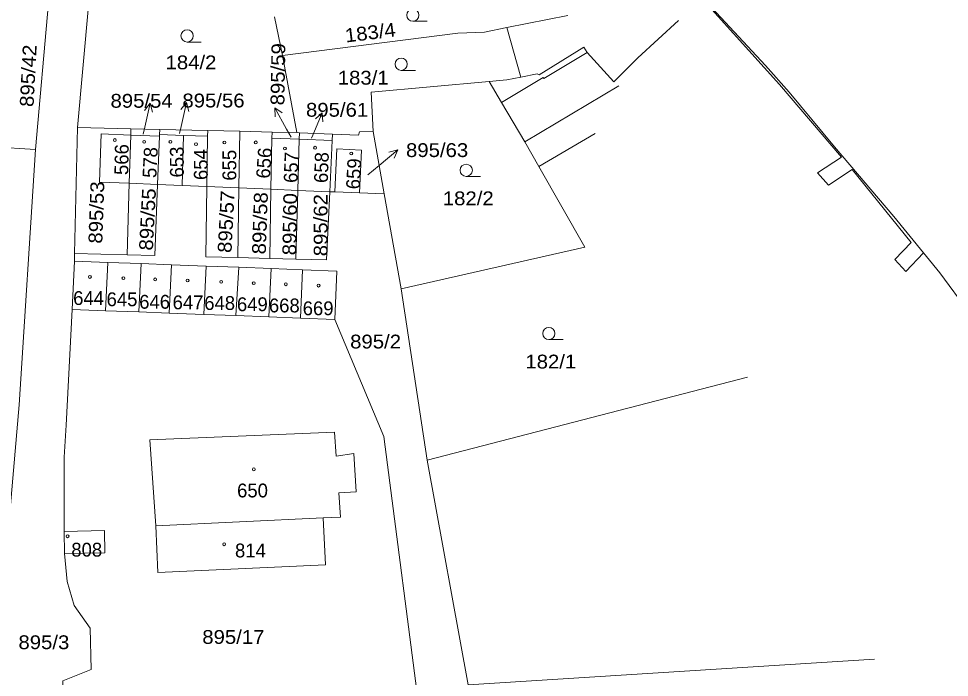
# Model space of a CAD drawing. Extents: x -686207 to -681951, y -1020493 to -1017811.
# Drawn here: x -682393.2 to -682278.7, y -1019020.1 to -1018939.1 of the extents above; entities that cross this region are included whole.
import ezdxf

# ---------------------------------------------------------------- set-up
doc = ezdxf.new("R2010")
doc.units = 0
doc.header["$LTSCALE"] = 0.4
for name, color, linetype, lineweight in [('1', 7, 'Continuous', 13), ('13', 7, 'Continuous', 13), ('3', 7, 'Continuous', 13), ('4', 7, 'Continuous', 13), ('5', 7, 'Continuous', 13), ('7', 7, 'Continuous', 13)]:
    doc.layers.add(name, color=color, linetype=linetype, lineweight=lineweight)
doc.layers.add('2', color=7, linetype='Continuous')

msp = doc.modelspace()

# ---------------------------------------------------------------- linework, layer by layer
at = {"layer": '1'}
for p, q in [((-682361.73, -1018938.86), (-682360.73, -1018943.62)), ((-682325.63, -1018938.69), (-682333.17, -1018940.2)), ((-682333.17, -1018940.2), (-682331.42, -1018946.27)), ((-682360.73, -1018943.62), (-682358.97, -1018953.11)), ((-682385.94, -1018952.47), (-682379.38, -1018952.63)), ((-682375.87, -1018953.34), (-682375.84, -1018952.71)), ((-682375.84, -1018952.71), (-682369.92, -1018952.85)), ((-682375.88, -1018953.53), (-682379.4, -1018953.4)), ((-682375.87, -1018953.34), (-682375.88, -1018953.53)), ((-682372.91, -1018953.45), (-682375.87, -1018953.34)), ((-682373.06, -1018959.61), (-682372.91, -1018953.45)), ((-682369.95, -1018953.56), (-682372.91, -1018953.45)), ((-682370.04, -1018959.74), (-682369.95, -1018953.56)), ((-682369.92, -1018952.85), (-682369.95, -1018953.56)), ((-682369.92, -1018952.85), (-682365.98, -1018952.94)), ((-682366.1, -1018959.9), (-682365.98, -1018952.94)), ((-682365.98, -1018952.94), (-682362.03, -1018953.04)), ((-682362.05, -1018953.79), (-682362.16, -1018960.07)), ((-682362.03, -1018953.04), (-682358.97, -1018953.11)), ((-682358.97, -1018953.11), (-682358.66, -1018953.12)), ((-682358.66, -1018953.12), (-682354.58, -1018953.28)), ((-682354.62, -1018954.08), (-682354.58, -1018953.28)), ((-682349.59, -1018952.99), (-682348.23, -1018960.64)), ((-682379.85, -1018968.13), (-682379.58, -1018959.33)), ((-682376.1, -1018959.48), (-682373.06, -1018959.61)), ((-682373.06, -1018959.61), (-682370.04, -1018959.74)), ((-682370.04, -1018959.74), (-682366.1, -1018959.9)), ((-682366.1, -1018959.9), (-682362.16, -1018960.07)), ((-682359.08, -1018968.66), (-682358.85, -1018960.21)), ((-682354.29, -1018960.4), (-682354.93, -1018960.37)), ((-682348.23, -1018960.64), (-682351.26, -1018960.52)), ((-682348.23, -1018960.64), (-682346.16, -1018972.32)), ((-682379.85, -1018968.13), (-682386.3, -1018967.97)), ((-682386.32, -1018968.9), (-682386.61, -1018974.84)), ((-682382.23, -1018969.06), (-682386.32, -1018968.9)), ((-682382.49, -1018975), (-682382.23, -1018969.06)), ((-682378.11, -1018969.22), (-682382.23, -1018969.06)), ((-682378.39, -1018975.15), (-682378.11, -1018969.22)), ((-682374.68, -1018975.29), (-682374.41, -1018969.36)), ((-682370.4, -1018975.46), (-682370.14, -1018969.52)), ((-682366.12, -1018969.67), (-682370.14, -1018969.52)), ((-682366.46, -1018975.61), (-682366.12, -1018969.67)), ((-682362.12, -1018969.82), (-682366.12, -1018969.67)), ((-682362.41, -1018975.76), (-682362.12, -1018969.82)), ((-682358.28, -1018969.97), (-682362.12, -1018969.82)), ((-682358.53, -1018975.91), (-682358.28, -1018969.97)), ((-682346.16, -1018972.32), (-682342.94, -1018993.38)), ((-682382.49, -1018975), (-682378.39, -1018975.15)), ((-682366.46, -1018975.61), (-682362.41, -1018975.76)), ((-682362.41, -1018975.76), (-682358.53, -1018975.91)), ((-682358.53, -1018975.91), (-682354.3, -1018976.07)), ((-682303.55, -1018983.18), (-682342.94, -1018993.38)), ((-682376.33, -1019001.45), (-682355.73, -1019000.49)), ((-682387.59, -1019002.15), (-682387.56, -1019004.85)), ((-682337.89, -1019021), (-682287.95, -1019017.83))]:
    msp.add_line(p, q, dxfattribs=at)
for points in [[(-682276.34, -1018975.17), (-682279.9, -1018970.36), (-682285.55, -1018963.44), (-682292.84, -1018954.85), (-682298.41, -1018948.14), (-682301.32, -1018944.85), (-682314.55, -1018930.63), (-682342.21, -1018901.37), (-682348.46, -1018895.5), (-682353.78, -1018891.13), (-682359.01, -1018887.98), (-682365.23, -1018884.61), (-682377.11, -1018878.94), (-682378.97, -1018879.84), (-682381.2, -1018881.17)], [(-682383.5, -1018926.17), (-682384.6, -1018937.53), (-682385.94, -1018952.47)], [(-682389.52, -1018937.15), (-682391.12, -1018955.18), (-682396.38, -1018954.85)], [(-682331.42, -1018946.27), (-682329.42, -1018945.86), (-682329.18, -1018945.99), (-682323.67, -1018942.62), (-682323.29, -1018943.26), (-682320.01, -1018946.88), (-682319.8, -1018946.67), (-682317.04, -1018943.92), (-682312.04, -1018939.32)], [(-682333.17, -1018940.2), (-682335.91, -1018940.75), (-682339.16, -1018940.89), (-682360.73, -1018943.62)], [(-682335.31, -1018946.82), (-682349.85, -1018948.12), (-682349.59, -1018952.99)], [(-682335.31, -1018946.82), (-682333.79, -1018949.39), (-682330.92, -1018954.26), (-682329.2, -1018957.27), (-682323.56, -1018967.21), (-682346.16, -1018972.32)], [(-682331.42, -1018946.27), (-682333.14, -1018946.62), (-682335.31, -1018946.82)], [(-682386.32, -1018968.9), (-682386.3, -1018967.97), (-682385.94, -1018952.47)], [(-682379.4, -1018953.4), (-682379.38, -1018952.63), (-682375.84, -1018952.71)], [(-682379.58, -1018959.33), (-682376.1, -1018959.48), (-682375.88, -1018953.53)], [(-682358.68, -1018953.92), (-682362.05, -1018953.79), (-682362.03, -1018953.04)], [(-682358.85, -1018960.21), (-682358.68, -1018953.92), (-682358.66, -1018953.12)], [(-682354.58, -1018953.28), (-682351.4, -1018953.4), (-682351.27, -1018953.02), (-682349.59, -1018952.99)], [(-682358.85, -1018960.21), (-682354.93, -1018960.37), (-682354.62, -1018954.08), (-682358.68, -1018953.92)], [(-682376.1, -1018959.48), (-682376.42, -1018968.22), (-682379.85, -1018968.13)], [(-682366.25, -1018968.48), (-682370.17, -1018968.38), (-682370.04, -1018959.74)], [(-682362.31, -1018968.58), (-682366.25, -1018968.48), (-682366.1, -1018959.9)], [(-682359.08, -1018968.66), (-682362.31, -1018968.58), (-682362.16, -1018960.07), (-682358.85, -1018960.21)], [(-682354.93, -1018960.37), (-682355.34, -1018968.76), (-682359.08, -1018968.66)], [(-682370.14, -1018969.52), (-682374.41, -1018969.36), (-682378.11, -1018969.22)], [(-682354.3, -1018976.07), (-682354.05, -1018970.13), (-682358.28, -1018969.97)], [(-682387.59, -1019002.15), (-682387.6, -1018993.01), (-682387.35, -1018989.09), (-682386.61, -1018974.84), (-682382.49, -1018975)], [(-682378.39, -1018975.15), (-682374.68, -1018975.29), (-682370.4, -1018975.46), (-682366.46, -1018975.61)], [(-682343.65, -1019026.23), (-682348.28, -1018990.46), (-682354.3, -1018976.07)], [(-682355.73, -1019000.49), (-682353.6, -1019000.39), (-682353.81, -1018997.41), (-682351.67, -1018997.29), (-682351.97, -1018992.58), (-682354.13, -1018992.91), (-682354.35, -1018989.93), (-682377.06, -1018990.9), (-682376.33, -1019001.45)], [(-682342.94, -1018993.38), (-682337.89, -1019021), (-682337.02, -1019026.08), (-682343.65, -1019026.23)], [(-682376.33, -1019001.45), (-682376.06, -1019007.2), (-682355.46, -1019006.25), (-682355.73, -1019000.49)], [(-682387.56, -1019004.85), (-682382.59, -1019004.78), (-682382.62, -1019002.02), (-682387.59, -1019002.15)], [(-682387.9, -1019028.52), (-682387.75, -1019020.5), (-682384.26, -1019019.14), (-682384.4, -1019014.03), (-682386.34, -1019011.27), (-682387.24, -1019008.31), (-682387.56, -1019004.85)]]:
    msp.add_lwpolyline(points, dxfattribs=at)
for points in [[(-682379.4, -1018953.4), (-682383.03, -1018953.27), (-682383.24, -1018959.18), (-682379.58, -1018959.33)], [(-682351.26, -1018960.52), (-682351.01, -1018955.26), (-682354.05, -1018955.12), (-682354.29, -1018960.4)]]:
    msp.add_lwpolyline(points, close=True, dxfattribs=at)
at = {"layer": '13'}
msp.add_lwpolyline([(-682284.1, -1018970.2), (-682281.91, -1018967.9), (-682285.55, -1018963.44), (-682292.84, -1018954.85), (-682298.41, -1018948.14), (-682301.32, -1018944.85), (-682314.55, -1018930.63), (-682329.2, -1018915.14), (-682316.6, -1018929.11), (-682309.05, -1018936.69), (-682299.6, -1018947.21), (-682291.99, -1018956.11), (-682294.95, -1018958.04), (-682293.61, -1018959.56), (-682290.7, -1018957.66), (-682283.43, -1018966.6), (-682285.45, -1018968.71)], close=True, dxfattribs=at)
at = {"layer": '3'}
for p, q in [((-682344.703, -1018939.41), (-682342.953, -1018939.41)), ((-682372.473, -1018941.97), (-682370.723, -1018941.97)), ((-682346.153, -1018945.45), (-682344.403, -1018945.45)), ((-682338.143, -1018958.49), (-682336.393, -1018958.49)), ((-682327.993, -1018978.56), (-682326.243, -1018978.56))]:
    msp.add_line(p, q, dxfattribs=at)
for centre in [(-682344.7029, -1018938.6598), (-682372.4729, -1018941.2198), (-682346.1529, -1018944.6998), (-682338.1429, -1018957.7398), (-682327.9929, -1018977.8098)]:
    msp.add_circle(centre, 0.75, dxfattribs=at)
at = {"layer": '4'}
for p, q in [((-682328.62, -1018946.44), (-682323.29, -1018943.26)), ((-682330.92, -1018954.26), (-682319.39, -1018947.35)), ((-682329.2, -1018957.27), (-682322.28, -1018953.23)), ((-682393.12, -1018986.59), (-682391.12, -1018955.18)), ((-682396.76, -1019028.35), (-682393.12, -1018986.59))]:
    msp.add_line(p, q, dxfattribs=at)
msp.add_lwpolyline([(-682333.79, -1018949.39), (-682328.68, -1018946.34), (-682328.62, -1018946.44)], dxfattribs=at)
at = {"layer": '5'}
for centre in [(-682381.3568, -1018954.0192), (-682377.7468, -1018954.2492), (-682374.5268, -1018954.2492), (-682371.3768, -1018954.5192), (-682367.8868, -1018954.3292), (-682364.0368, -1018954.3092), (-682360.4368, -1018955.0692), (-682356.7368, -1018954.9592), (-682352.2768, -1018955.6692), (-682384.4168, -1018970.8492), (-682380.3068, -1018970.9992), (-682376.3968, -1018971.1492), (-682372.4068, -1018971.2992), (-682368.2868, -1018971.4592), (-682364.2768, -1018971.6092), (-682360.3368, -1018971.7592), (-682356.2968, -1018971.9192), (-682364.2568, -1018994.5092), (-682387.1668, -1019002.7392), (-682367.9068, -1019003.7292)]:
    msp.add_circle(centre, 0.175, dxfattribs=at)
at = {"layer": '7'}
for p, q in [((-682377.005, -1018949.506), (-682377.718, -1018950.369)), ((-682372.525, -1018949.416), (-682373.238, -1018950.279)), ((-682361.695, -1018950.055), (-682361.647, -1018951.174)), ((-682355.847, -1018950.678), (-682356.7, -1018951.404)), ((-682373.39, -1018953.2), (-682373.2, -1018952.34)), ((-682359.68, -1018953.68), (-682360.24, -1018952.68)), ((-682357.16, -1018953.77), (-682357.02, -1018953.44)), ((-682346.561, -1018955.241), (-682347.65, -1018955.501)), ((-682350.23, -1018958.3), (-682348.86, -1018957.17))]:
    msp.add_line(p, q, dxfattribs=at)
for points in [[(-682377.87, -1018953.29), (-682377.68, -1018952.43), (-682377.005, -1018949.506), (-682376.742, -1018950.594)], [(-682373.2, -1018952.34), (-682372.525, -1018949.416), (-682372.262, -1018950.504)], [(-682360.24, -1018952.68), (-682361.695, -1018950.055), (-682360.771, -1018950.688)], [(-682357.02, -1018953.44), (-682355.847, -1018950.678), (-682355.778, -1018951.795)], [(-682348.86, -1018957.17), (-682346.561, -1018955.241), (-682347.006, -1018956.268)]]:
    msp.add_lwpolyline(points, dxfattribs=at)

# ---------------------------------------------------------------- texts
at = {"layer": '2', "width": 1.1}
for s, rotation, p in [('183/4', 7, (-682352.949, -1018942.031)), ('895/42', 87, (-682391.364, -1018949.985)), ('895/59', 89, (-682360.517, -1018949.769)), ('895/53', 88, (-682382.91, -1018966.779)), ('895/55', 87, (-682376.691, -1018967.644)), ('895/57', 87, (-682367.021, -1018967.934)), ('895/58', 88, (-682362.8, -1018968.099)), ('895/60', 89, (-682359.06, -1018968.204)), ('895/62', 90, (-682355.2, -1018968.31))]:
    msp.add_text(s, height=1.7, rotation=rotation, dxfattribs=at).set_placement(p)
for s, p in [('184/2', (-682375.123, -1018945.32)), ('183/1', (-682353.943, -1018947.21)), ('895/54', (-682381.891, -1018950.049)), ('895/56', (-682373.051, -1018950.01)), ('895/61', (-682357.85, -1018951.15)), ('895/63', (-682345.55, -1018956.11)), ('182/2', (-682341.023, -1018962.039)), ('895/2', (-682352.42, -1018979.65)), ('182/1', (-682330.873, -1018982.11)), ('895/17', (-682370.605, -1019015.97)), ('895/3', (-682393.213, -1019016.62))]:
    msp.add_text(s, height=1.7, dxfattribs=at).set_placement(p)
at = {"layer": '2'}
for s, rotation, p in [('566', 89, (-682379.714, -1018958.329)), ('578', 87, (-682376.264, -1018958.716)), ('653', 90, (-682372.88, -1018958.624)), ('654', 90, (-682369.94, -1018958.934)), ('655', 90, (-682366.42, -1018959.014)), ('656', 86, (-682362.299, -1018958.799)), ('657', 88, (-682358.899, -1018959.313)), ('658', 88, (-682355.169, -1018959.323)), ('659', 87, (-682351.234, -1018960.106))]:
    msp.add_text(s, height=1.7, rotation=rotation, dxfattribs=at).set_placement(p)
for s, p in [('644', (-682386.484, -1018974.299)), ('645', (-682382.374, -1018974.45)), ('646', (-682378.364, -1018974.76)), ('647', (-682374.254, -1018974.83)), ('648', (-682370.364, -1018974.91)), ('649', (-682366.344, -1018975.059)), ('668', (-682362.414, -1018975.21)), ('669', (-682358.254, -1018975.559)), ('650', (-682366.324, -1018997.96)), ('808', (-682386.71, -1019005.24)), ('814', (-682366.58, -1019005.34))]:
    msp.add_text(s, height=1.7, dxfattribs=at).set_placement(p)

doc.saveas('drawing.dxf')
